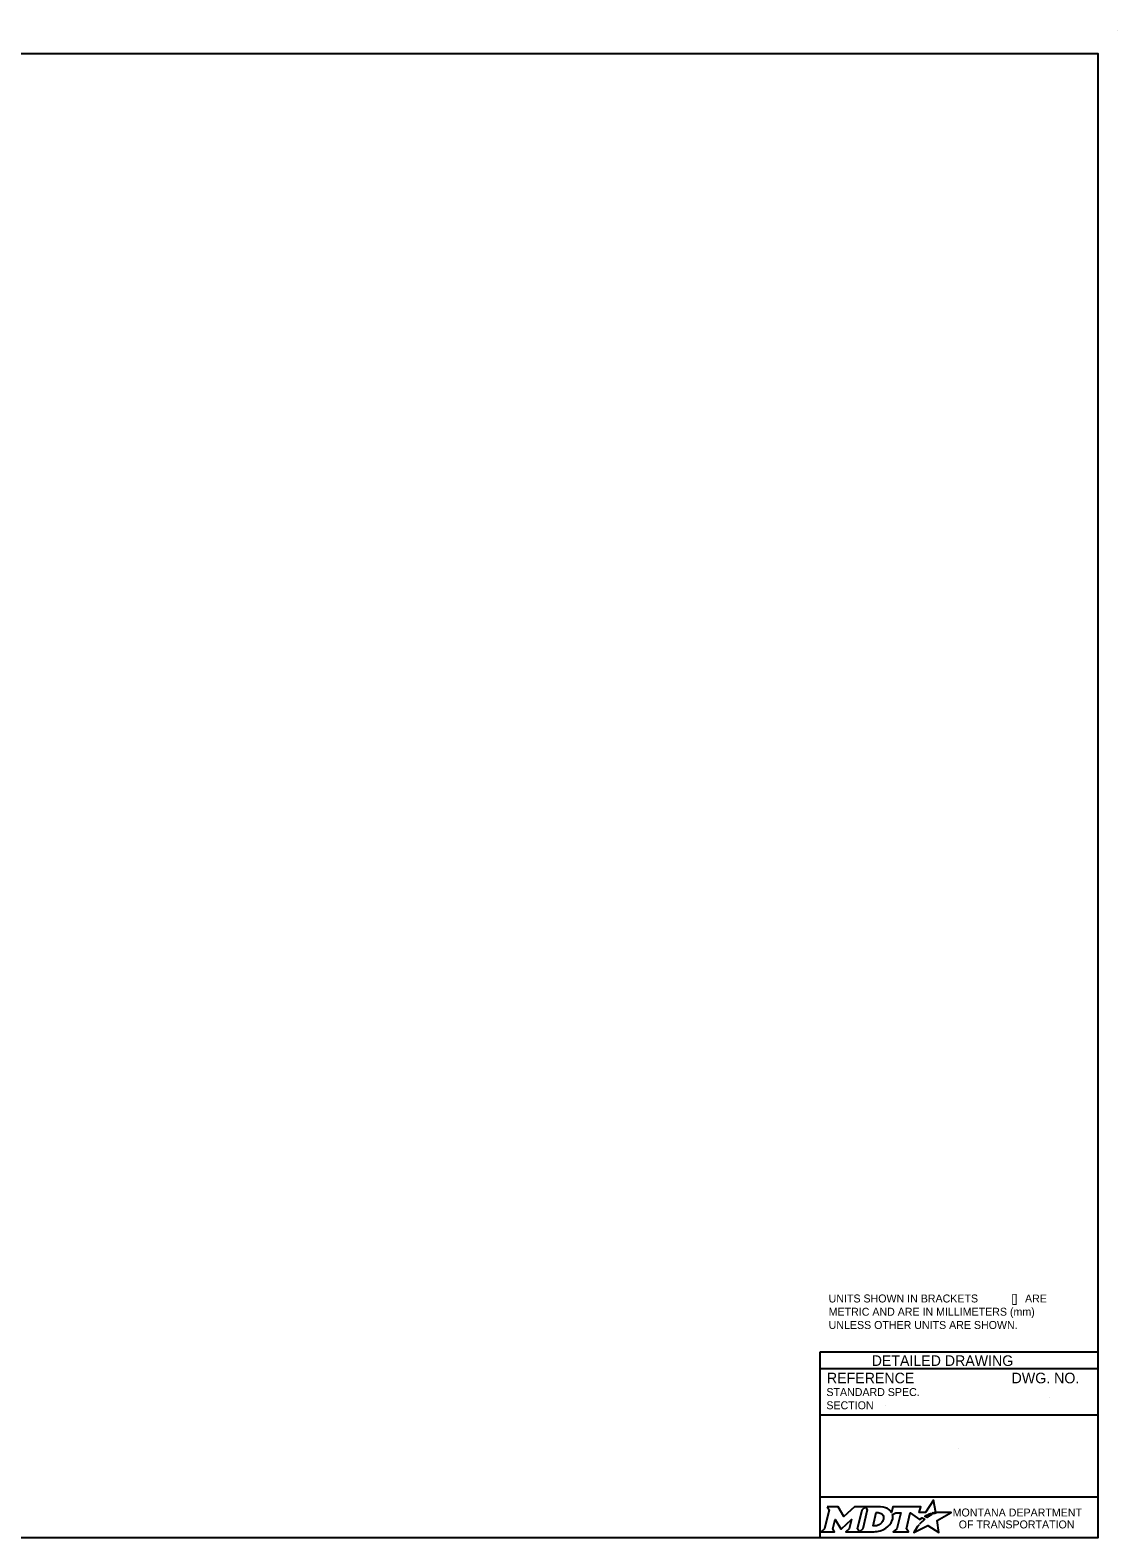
# Model space of a CAD drawing. Extents: x 49991.4 to 50021, y 49987.6 to 50011.4.
# Drawn here: x 50008.69 to 50016.9, y 49987.8 to 49999.18 of the extents above; entities that cross this region are included whole.
import ezdxf

# ---------------------------------------------------------------- set-up
doc = ezdxf.new("R2010")
doc.units = 0
for name, color, linetype in [('Default', 7, 'Continuous'), ('Level 1', 7, 'Continuous'), ('Level 2', 7, 'Continuous'), ('Level 5', 7, 'Continuous')]:
    doc.layers.add(name, color=color, linetype=linetype)

msp = doc.modelspace()

# ---------------------------------------------------------------- linework, layer by layer
at = {"layer": 'Default'}
for points in [[(50015.513, 49987.981), (50015.502, 49987.987), (50015.514, 49987.99), (50015.526, 49987.991), (50015.508, 49988.082), (50015.449, 49987.99), (50015.401, 49987.99), (50015.412, 49988.034), (50015.202, 49988.034), (50015.192, 49987.991), (50015.186, 49988)], [(50014.706, 49988.034), (50014.72, 49988.01), (50014.686, 49987.867), (50014.66, 49987.845), (50014.762, 49987.845), (50014.749, 49987.867), (50014.765, 49987.937), (50014.809, 49987.868), (50014.814, 49987.868), (50014.889, 49987.938), (50014.872, 49987.867), (50014.848, 49987.845), (50014.949, 49987.845), (50014.936, 49987.868), (50014.969, 49988.011)], [(50014.969, 49988.011), (50014.994, 49988.034), (50014.912, 49988.034), (50014.832, 49987.961), (50014.788, 49988.034), (50014.706, 49988.034)], [(50015.108, 49988.034), (50014.994, 49988.034), (50015.009, 49988.011), (50014.975, 49987.867), (50014.949, 49987.845), (50015.06, 49987.845)], [(50015.132, 49987.947), (50015.13, 49987.939), (50015.127, 49987.93), (50015.123, 49987.922), (50015.118, 49987.914), (50015.111, 49987.907), (50015.103, 49987.901), (50015.095, 49987.896), (50015.086, 49987.892), (50015.077, 49987.89), (50015.067, 49987.889), (50015.052, 49987.889), (50015.075, 49987.989), (50015.091, 49987.989), (50015.099, 49987.988), (50015.106, 49987.986), (50015.113, 49987.983), (50015.119, 49987.979), (50015.124, 49987.974), (50015.128, 49987.968), (50015.13, 49987.962), (50015.132, 49987.955), (50015.132, 49987.952), (50015.132, 49987.947)], [(50015.199, 49987.975), (50015.224, 49987.988), (50015.261, 49987.988), (50015.232, 49987.867), (50015.205, 49987.845), (50015.321, 49987.845), (50015.304, 49987.867), (50015.332, 49987.988), (50015.403, 49987.936), (50015.424, 49987.951), (50015.444, 49987.94)], [(50015.388, 49987.884), (50015.373, 49987.86), (50015.368, 49987.852), (50015.362, 49987.844), (50015.36, 49987.839), (50015.465, 49987.893), (50015.549, 49987.838), (50015.536, 49987.93), (50015.643, 49987.989), (50015.594, 49987.989), (50015.564, 49987.99), (50015.543, 49987.99), (50015.536, 49987.989), (50015.531, 49987.987), (50015.523, 49987.985), (50015.513, 49987.981)], [(50015.462, 49987.954), (50015.46, 49987.952), (50015.442, 49987.961), (50015.452, 49987.967), (50015.456, 49987.969), (50015.465, 49987.973), (50015.47, 49987.976), (50015.478, 49987.979), (50015.485, 49987.982), (50015.497, 49987.974), (50015.493, 49987.972), (50015.489, 49987.97), (50015.484, 49987.967), (50015.479, 49987.965), (50015.478, 49987.963), (50015.475, 49987.962), (50015.472, 49987.96), (50015.47, 49987.959), (50015.467, 49987.957), (50015.465, 49987.955), (50015.462, 49987.954)], [(50015.106, 49987.852), (50015.114, 49987.855), (50015.127, 49987.86), (50015.148, 49987.871)], [(50015.402, 49987.9), (50015.402, 49987.9)]]:
    msp.add_lwpolyline(points, dxfattribs=at)
for centre, radius, start, end in [((50015.087, 49987.973), 0.118, 300.9103, 339.1383), ((50015.131, 49987.955), 0.0709, 339.5329, 15.8582)]:
    msp.add_arc(centre, radius, start, end, dxfattribs=at)
for centre, major_axis, ratio, start_param, end_param in [((50015.106, 49987.986), (0.0834, -0.0037), 0.568097, 0.61298, 1.570796), ((50015.161, 49987.994), (0.0361, -0.0295), 0.469099, 1.225588, 1.570796), ((50015.433, 49987.93), (-0.0112, -0.0097), 0.021651, 3.157348, 6.283185), ((50015.06, 49987.993), (0, 0.148), 0.987302, 3.139398, 3.456847), ((50015.395, 49987.892), (-0.00694, -0.00806), 0.008222, 0, 3.137361), ((50015.412, 49987.911), (-0.0098, -0.0102), 0.016458, 3.141593, 6.279097)]:
    msp.add_ellipse(centre, major_axis=major_axis, ratio=ratio, start_param=start_param, end_param=end_param, dxfattribs=at)
at = {"layer": 'Level 1'}
msp.add_line((50016.9, 49999.176), (50016.9, 49999.176), dxfattribs=at)
msp.add_lwpolyline([(49999.384, 49998.999), (50016.75, 49998.999), (50016.75, 49987.799), (49999.384, 49987.799)], close=True, dxfattribs=at)
at = {"layer": 'Level 5'}
for p, q in [((50016.75, 49989.199), (50014.65, 49989.199)), ((50014.65, 49989.199), (50014.65, 49987.799)), ((50016.75, 49989.074), (50014.65, 49989.074)), ((50016.386, 49988.859), (50016.386, 49988.859)), ((50016.75, 49988.724), (50014.65, 49988.724)), ((50015.144, 49988.799), (50015.144, 49988.799)), ((50015.7, 49988.475), (50015.7, 49988.475)), ((50016.75, 49988.106), (50014.65, 49988.106))]:
    msp.add_line(p, q, dxfattribs=at)

# ---------------------------------------------------------------- texts
at = {"layer": 'Default'}
for s, p in [('MONTANA DEPARTMENT', (50015.653, 49987.96)), ('OF TRANSPORTATION', (50015.699, 49987.87))]:
    msp.add_text(s, height=0.06, rotation=360, dxfattribs=at).set_placement(p)
at = {"layer": 'Level 2'}
for s, p in [('UNITS SHOWN IN BRACKETS ', (50014.717, 49989.575)), ('[]', (50016.097, 49989.575)), (' ARE ', (50016.177, 49989.575)), ('METRIC AND ARE IN MILLIMETERS (mm) ', (50014.717, 49989.475)), ('UNLESS OTHER UNITS ARE SHOWN.', (50014.717, 49989.375))]:
    msp.add_text(s, height=0.06, dxfattribs=at).set_placement(p)
at = {"layer": 'Level 5'}
for s, height, p in [('DETAILED DRAWING', 0.0799, (50015.042, 49989.096)), ('REFERENCE', 0.08, (50014.704, 49988.965)), ('DWG. NO.', 0.08, (50016.098, 49988.965)), ('STANDARD SPEC.', 0.06, (50014.7, 49988.869)), ('SECTION', 0.06, (50014.7, 49988.769))]:
    msp.add_text(s, height=height, dxfattribs=at).set_placement(p)

doc.saveas('drawing.dxf')
